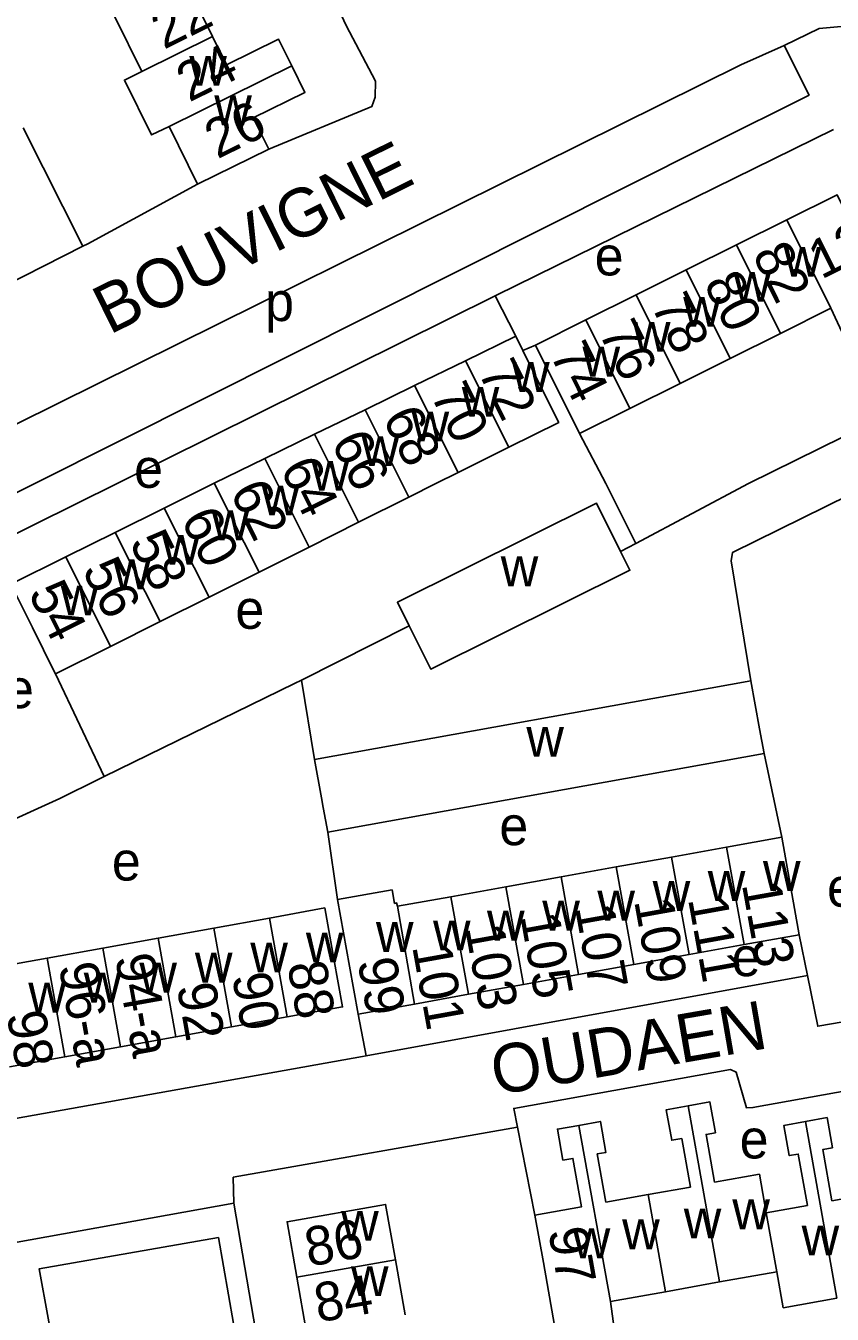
# Model space of a CAD drawing. Extents: x 157794 to 159375, y 380877 to 382306.
# Drawn here: x 158354 to 158437, y 381414.5 to 381547.1 of the extents above; entities that cross this region are included whole.
import ezdxf

# ---------------------------------------------------------------- set-up
doc = ezdxf.new("R2010")
doc.units = 0
for name, color, linetype in [('BLT_Basislijn', 7, 'Continuous'), ('BLT_Bebouwing', 7, 'Continuous'), ('BLT_Centroide', 7, 'Continuous'), ('BLT_Huisnummer', 7, 'Continuous'), ('BLT_Huisnummer_ tussenligend', 7, 'Continuous'), ('BLT_Huisnummer_reeks', 7, 'Continuous'), ('BLT_Onderverdeling_panden', 7, 'Continuous'), ('BLT_Straatnaam', 7, 'Continuous')]:
    doc.layers.add(name, color=color, linetype=linetype)

msp = doc.modelspace()

# ---------------------------------------------------------------- linework, layer by layer
at = {"layer": 'BLT_Basislijn'}
for p, q in [((158359.89, 381524.44), (158353.74, 381536.64)), ((158404.43, 381515.17), (158402.32, 381519.33)), ((158405.16, 381513.72), (158406.47, 381514.27)), ((158416.79, 381493.84), (158415.22, 381493.01)), ((158382.37, 381479.77), (158393.48, 381485.34)), ((158357.06, 381480.4), (158362.08, 381469.83)), ((158382.37, 381479.77), (158383.74, 381471.58)), ((158431.81, 381463.59), (158429.99, 381472.2)), ((158357.53, 381467.58), (158350.52, 381464.39)), ((158386.08, 381457.16), (158385.09, 381464.1)), ((158433.62, 381453.55), (158434.46, 381449.35)), ((158389.04, 381441.08), (158434.46, 381449.35)), ((158388.21, 381445.36), (158389.04, 381441.08)), ((158406.41, 381424.67), (158404.63, 381433.72)), ((158375.43, 381425.92), (158348.3, 381421.02)), ((158380.03, 381399.02), (158375.43, 381425.92))]:
    msp.add_line(p, q, dxfattribs=at)
for points in [[(158379.01, 381534.43), (158389.61, 381538.83), (158389.96, 381539.81), (158389.99, 381541.44), (158386.97, 381547.16), (158375.23, 381572.49), (158369.82, 381587.16)], [(158432.05, 381545.11), (158435.65, 381546.85), (158438.67, 381547.13), (158439.79, 381546.85), (158442.01, 381544.7), (158444.4, 381540.04)], [(158432.05, 381545.11), (158427.59, 381543.14), (158340.66, 381500), (158326.22, 381492.89), (158322.69, 381489.48), (158322.78, 381485.57), (158323.33, 381484.58)], [(158432.05, 381545.11), (158434.63, 381540.01), (158424.45, 381534.91), (158354.95, 381500), (158345.29, 381495.16), (158323.33, 381484.58)], [(158437.14, 381536.48), (158402.44, 381519.39), (158402.32, 381519.33)], [(158371.69, 381530.82), (158360.4, 381524.7), (158359.89, 381524.44)], [(158281.44, 381482.74), (158282.1, 381483.17), (158295.26, 381491.61), (158311.81, 381500), (158359.89, 381524.44)], [(158402.32, 381519.33), (158363.43, 381500), (158350.57, 381493.67)], [(158450.23, 381510.78), (158428.38, 381500), (158416.79, 381493.84)], [(158428.64, 381479.68), (158426.62, 381492.06), (158426.74, 381492.89), (158441.15, 381500), (158454.58, 381506.47)], [(158411, 381505.17), (158413.7, 381500), (158416.79, 381493.84)], [(158362.08, 381469.83), (158381.65, 381479.41), (158382.37, 381479.77)], [(158357.53, 381467.58), (158361.53, 381469.56), (158362.08, 381469.83)], [(158434.46, 381449.35), (158435.52, 381444.13), (158464.58, 381449.11)], [(158389.04, 381441.08), (158388.65, 381441.01), (158347.73, 381433.71), (158347.43, 381433.69)], [(158404.63, 381433.72), (158404.24, 381435.67), (158426.55, 381439.67), (158427.12, 381439.4), (158428.2, 381435.71), (158428.84, 381435.74), (158461.58, 381441.62), (158462.15, 381441.73)], [(158375.43, 381425.92), (158375.36, 381428.57), (158404.63, 381433.72)], [(158373.84, 381422.36), (158355.39, 381419.16), (158358.15, 381403.9), (158363.16, 381405.02), (158365.35, 381403.76), (158366.31, 381398.82), (158373.98, 381400.19), (158372.95, 381402.04), (158372.62, 381404.82), (158373.43, 381407.49), (158374.04, 381407.91), (158375, 381409.38), (158375.35, 381410.51), (158375.39, 381413.51), (158373.84, 381422.36)]]:
    msp.add_lwpolyline(points, dxfattribs=at)
at = {"layer": 'BLT_Bebouwing'}
for p, q in [((158365.95, 381542.44), (158363.17, 381548.08)), ((158371.69, 381530.82), (158368.75, 381536.78)), ((158379.01, 381534.43), (158371.69, 381530.82)), ((158427.17, 381524.58), (158432.35, 381527.15)), ((158421.99, 381522), (158427.17, 381524.58)), ((158416.82, 381519.43), (158421.99, 381522)), ((158411.64, 381516.85), (158416.82, 381519.43)), ((158436.88, 381518.05), (158431.7, 381515.47)), ((158406.47, 381514.27), (158411.64, 381516.85)), ((158431.7, 381515.47), (158426.52, 381512.9)), ((158404.43, 381515.17), (158399.27, 381512.65)), ((158405.16, 381513.72), (158404.43, 381515.17)), ((158411, 381505.17), (158406.47, 381514.27)), ((158426.52, 381512.9), (158421.35, 381510.32)), ((158399.27, 381512.65), (158394.03, 381510.09)), ((158394.03, 381510.09), (158388.93, 381507.61)), ((158421.35, 381510.32), (158416.17, 381507.74)), ((158388.93, 381507.61), (158383.73, 381505.08)), ((158416.17, 381507.74), (158411, 381505.17)), ((158383.73, 381505.08), (158378.6, 381502.57)), ((158378.6, 381502.57), (158373.41, 381500.04)), ((158378.6, 381502.57), (158383.17, 381493.47)), ((158388.26, 381496.02), (158393.43, 381498.61)), ((158363.22, 381494.98), (158368.25, 381497.48)), ((158383.17, 381493.47), (158388.26, 381496.02)), ((158358.14, 381492.46), (158363.22, 381494.98)), ((158378.03, 381490.89), (158383.17, 381493.47)), ((158352.48, 381489.64), (158358.14, 381492.46)), ((158372.87, 381488.31), (158378.03, 381490.89)), ((158367.85, 381485.8), (158372.87, 381488.31)), ((158362.73, 381483.23), (158367.85, 381485.8)), ((158357.06, 381480.4), (158362.73, 381483.23)), ((158428.64, 381479.68), (158383.74, 381471.58)), ((158383.74, 381471.58), (158384.44, 381467.66)), ((158429.99, 381472.2), (158385.09, 381464.1)), ((158420.46, 381461.55), (158426.13, 381462.57)), ((158426.13, 381462.57), (158431.81, 381463.59)), ((158414.78, 381460.53), (158420.46, 381461.55)), ((158409.1, 381459.51), (158414.78, 381460.53)), ((158397.75, 381457.46), (158403.42, 381458.48)), ((158403.42, 381458.48), (158409.1, 381459.51)), ((158392.27, 381456.48), (158397.75, 381457.46)), ((158379.08, 381455.27), (158373.36, 381454.23)), ((158367.64, 381453.2), (158361.93, 381452.17)), ((158373.36, 381454.23), (158367.64, 381453.2)), ((158433.62, 381453.55), (158427.95, 381452.53)), ((158361.93, 381452.17), (158356.21, 381451.14)), ((158427.95, 381452.53), (158422.27, 381451.5)), ((158356.21, 381451.14), (158350.49, 381450.11)), ((158416.59, 381450.48), (158410.91, 381449.46)), ((158422.27, 381451.5), (158416.59, 381450.48)), ((158410.91, 381449.46), (158405.24, 381448.43)), ((158405.24, 381448.43), (158399.56, 381447.41)), ((158394.01, 381446.41), (158388.21, 381445.36)), ((158399.56, 381447.41), (158394.01, 381446.41)), ((158375.19, 381444.06), (158380.91, 381445.09)), ((158369.47, 381443.03), (158375.19, 381444.06)), ((158363.76, 381442), (158369.47, 381443.03)), ((158358.04, 381440.97), (158363.76, 381442)), ((158352.32, 381439.94), (158358.04, 381440.97)), ((158392.05, 381420.08), (158393.05, 381414.39)), ((158425.42, 381417.79), (158431.31, 381418.84)), ((158382.91, 381412.6), (158381.9, 381418.29)), ((158419.85, 381416.79), (158425.42, 381417.79)), ((158414.18, 381415.78), (158419.85, 381416.79))]:
    msp.add_line(p, q, dxfattribs=at)
for points in [[(158375.84, 381554.34), (158377.18, 381551.63), (158371.78, 381548.96), (158373.23, 381546.04)], [(158373.23, 381546.04), (158374.67, 381543.11), (158380.03, 381545.76), (158381.39, 381543.02)], [(158368.75, 381536.78), (158366.96, 381535.9), (158364.16, 381541.56), (158365.95, 381542.44)], [(158381.39, 381543.02), (158382.74, 381540.28), (158377.41, 381537.65), (158379.01, 381534.43)], [(158432.35, 381527.15), (158437.52, 381529.73), (158442.05, 381520.62), (158441.81, 381520.5), (158443.25, 381517.6), (158438.24, 381515.11), (158436.88, 381518.05)], [(158403.72, 381503.74), (158408.86, 381506.31), (158406.52, 381511.01), (158405.16, 381513.72)], [(158398.5, 381501.14), (158403.72, 381503.74)], [(158393.43, 381498.61), (158396.21, 381500), (158398.5, 381501.14)], [(158368.25, 381497.48), (158373.32, 381500), (158373.41, 381500.04)], [(158415.22, 381493.01), (158412.76, 381497.97), (158392.26, 381487.79), (158393.48, 381485.34)], [(158393.48, 381485.34), (158395.69, 381480.9), (158416.18, 381491.08), (158415.22, 381493.01)], [(158357.06, 381480.4), (158356.98, 381480.58), (158354.69, 381485.19), (158352.48, 381489.64)], [(158429.99, 381472.2), (158429.52, 381474.76), (158428.64, 381479.68)], [(158384.44, 381467.66), (158384.62, 381466.66), (158385.09, 381464.1)], [(158431.81, 381463.59), (158432.75, 381458.39), (158433.62, 381453.55)], [(158386.08, 381457.16), (158391.71, 381458.17), (158391.96, 381456.78), (158392.18, 381456.82), (158392.27, 381456.48)], [(158388.21, 381445.36), (158387.31, 381450.31), (158386.08, 381457.16)], [(158380.91, 381445.09), (158386.62, 381446.12), (158385.73, 381451.06), (158384.78, 381456.3), (158379.08, 381455.27)], [(158418.06, 381426.79), (158422.41, 381427.57), (158421.52, 381432.56), (158420.49, 381432.38), (158419.93, 381435.53), (158422.17, 381435.93)], [(158422.17, 381435.93), (158424.42, 381436.33), (158424.99, 381433.16), (158424.02, 381432.99), (158424.9, 381428.07), (158429.51, 381428.89), (158430.22, 381424.92)], [(158434.25, 381434.31), (158436.48, 381434.71), (158437.03, 381431.61), (158436.04, 381431.43), (158436.98, 381426.16), (158441.37, 381426.94)], [(158406.41, 381424.67), (158411.22, 381425.53), (158410.32, 381430.52), (158409.3, 381430.34), (158408.73, 381433.53), (158410.94, 381433.92)], [(158410.94, 381433.92), (158413.15, 381434.32), (158413.71, 381431.13), (158412.83, 381430.97), (158413.71, 381426.02), (158418.06, 381426.79)], [(158430.22, 381424.92), (158434.46, 381425.68), (158433.52, 381430.96), (158432.58, 381430.8), (158432.03, 381433.91), (158434.25, 381434.31)], [(158381.9, 381418.29), (158380.9, 381423.99), (158391.04, 381425.78), (158392.05, 381420.08)], [(158408.68, 381411.95), (158407.28, 381419.79), (158406.41, 381424.67)], [(158431.31, 381418.84), (158431.97, 381415.14), (158437.5, 381416.13)], [(158408.68, 381411.95), (158414.56, 381413), (158414.18, 381415.78)]]:
    msp.add_lwpolyline(points, dxfattribs=at)
at = {"layer": 'BLT_Onderverdeling_panden'}
for p, q in [((158373.23, 381546.04), (158365.95, 381542.44)), ((158381.39, 381543.02), (158368.75, 381536.78)), ((158436.88, 381518.05), (158432.35, 381527.15)), ((158431.7, 381515.47), (158427.17, 381524.58)), ((158426.52, 381512.9), (158421.99, 381522)), ((158421.35, 381510.32), (158416.82, 381519.43)), ((158416.17, 381507.74), (158411.64, 381516.85)), ((158399.27, 381512.65), (158403.72, 381503.74)), ((158394.03, 381510.09), (158398.5, 381501.14)), ((158388.93, 381507.61), (158393.43, 381498.61)), ((158383.73, 381505.08), (158388.26, 381496.02)), ((158373.41, 381500.04), (158378.03, 381490.89)), ((158368.25, 381497.48), (158372.87, 381488.31)), ((158363.22, 381494.98), (158367.85, 381485.8)), ((158358.14, 381492.46), (158362.73, 381483.23)), ((158427.95, 381452.53), (158426.13, 381462.57)), ((158422.27, 381451.5), (158420.46, 381461.55)), ((158416.59, 381450.48), (158414.78, 381460.53)), ((158405.24, 381448.43), (158403.42, 381458.48)), ((158410.91, 381449.46), (158409.1, 381459.51)), ((158399.56, 381447.41), (158397.75, 381457.46)), ((158394.01, 381446.41), (158392.27, 381456.48)), ((158380.91, 381445.09), (158379.08, 381455.27)), ((158369.47, 381443.03), (158367.64, 381453.2)), ((158375.19, 381444.06), (158373.36, 381454.23)), ((158363.76, 381442), (158361.93, 381452.17)), ((158358.04, 381440.97), (158356.21, 381451.14)), ((158422.17, 381435.93), (158425.42, 381417.79)), ((158410.94, 381433.92), (158414.18, 381415.78)), ((158434.25, 381434.31), (158437.5, 381416.13)), ((158418.06, 381426.79), (158419.85, 381416.79)), ((158430.22, 381424.92), (158431.31, 381418.84)), ((158381.9, 381418.29), (158392.05, 381420.08))]:
    msp.add_line(p, q, dxfattribs=at)

# ---------------------------------------------------------------- texts
at = {"layer": 'BLT_Centroide'}
for s, p in [('w', (158370.84, 381540.97)), ('w', (158373.41, 381536.91)), ('e', (158412.56, 381521.44)), ('w', (158432.02, 381521.31)), ('w', (158426.84, 381518.73)), ('p', (158378.64, 381516.74)), ('w', (158421.67, 381516.16)), ('w', (158416.5, 381513.58)), ('w', (158411.31, 381511.02)), ('w', (158404.06, 381509.45)), ('w', (158398.88, 381506.89)), ('w', (158393.72, 381504.34)), ('w', (158388.58, 381501.81)), ('e', (158365.16, 381499.57)), ('w', (158383.42, 381499.27)), ('w', (158378.3, 381496.72)), ('w', (158373.14, 381494.17)), ('w', (158368.05, 381491.64)), ('w', (158363, 381489.12)), ('w', (158402.89, 381489.44)), ('w', (158357.61, 381486.42)), ('e', (158375.58, 381485.05)), ('e', (158351.87, 381476.88)), ('w', (158405.53, 381471.88)), ('e', (158402.75, 381462.77)), ('e', (158362.87, 381459.13)), ('w', (158429.88, 381458.06)), ('w', (158424.2, 381457.03)), ('w', (158418.53, 381456)), ('e', (158436.47, 381456.43)), ('w', (158407.17, 381453.97)), ('w', (158412.84, 381455)), ('w', (158401.48, 381452.94)), ('w', (158390.05, 381451.78)), ('w', (158395.92, 381451.94)), ('w', (158382.84, 381450.69)), ('w', (158371.42, 381448.62)), ('w', (158377.12, 381449.66)), ('e', (158426.66, 381449.28)), ('w', (158365.7, 381447.59)), ('w', (158359.98, 381446.56)), ('w', (158354.27, 381445.53)), ('e', (158427.48, 381430.51)), ('w', (158421.73, 381422.28)), ('w', (158426.73, 381423.22)), ('w', (158386.47, 381422.03)), ('w', (158415.39, 381421.16)), ('w', (158410.3, 381420.23)), ('w', (158433.86, 381420.52)), ('w', (158387.48, 381416.34))]:
    msp.add_text(s, height=4, dxfattribs=at).set_placement(p)
at = {"layer": 'BLT_Huisnummer'}
for s, rotation, p in [('26', 26.2747, (158373.73, 381533.38)), ('131', 26.4579, (158435.88, 381520.99)), ('82', 296.4213, (158428.73, 381523.62)), ('78', 296.4213, (158418.31, 381518.36)), ('74', 296.4213, (158407.9, 381513.34)), ('70', 296.4213, (158395.61, 381509.16)), ('66', 296.4213, (158385.38, 381504.25)), ('62', 296.4213, (158374.97, 381499.15)), ('58', 296.4213, (158364.62, 381493.94)), ('54', 296.4213, (158354.21, 381488.74)), ('113', 280.2212, (158427.7, 381458.75)), ('107', 280.2212, (158410.52, 381456.38)), ('103', 280.2212, (158399.2, 381454.31)), ('88', 280.2062, (158380.91, 381450.5)), ('99', 280.2212, (158388.14, 381450.85)), ('92', 280.2062, (158369.53, 381448.26)), ('86', 10.0202, (158383.11, 381419.36))]:
    msp.add_text(s, height=4, rotation=rotation, dxfattribs=at).set_placement(p)
at = {"layer": 'BLT_Huisnummer_ tussenligend'}
for s, rotation, p in [('22', 26.2747, (158368.22, 381544.67)), ('24', 26.2747, (158370.83, 381539.24)), ('80', 296.4213, (158423.73, 381520.61)), ('76', 296.4213, (158412.92, 381515.59)), ('72', 296.4213, (158400.51, 381511.53)), ('68', 296.4213, (158390.67, 381506.76)), ('64', 296.4213, (158380.13, 381501.54)), ('60', 296.4213, (158369.91, 381496.33)), ('56', 296.4213, (158359.76, 381491.12)), ('109', 280.2212, (158416.61, 381457.04)), ('111', 280.2212, (158422.16, 381457.23)), ('105', 280.2212, (158404.89, 381455.5)), ('101', 280.2212, (158393.77, 381452.34)), ('90', 280.2062, (158375.22, 381449.32)), ('98', 280.2062, (158352.02, 381445.38)), ('84', 10.0193, (158384.09, 381413.61))]:
    msp.add_text(s, height=4, rotation=rotation, dxfattribs=at).set_placement(p)
at = {"layer": 'BLT_Huisnummer_reeks'}
for s, rotation, p in [('96-a', 280.2062, (158357.39, 381450.37)), ('94-a', 280.2062, (158363.19, 381451.26)), ('97', 280.1184, (158407.77, 381423.11))]:
    msp.add_text(s, height=4, rotation=rotation, dxfattribs=at).set_placement(p)
at = {"layer": 'BLT_Straatnaam'}
for s, rotation, p in [('BOUVIGNE', 26.3903, (158362.62, 381515.29)), ('OUDAEN', 9.8134, (158402.36, 381437.01))]:
    msp.add_text(s, height=5, rotation=rotation, dxfattribs=at).set_placement(p)

doc.saveas('drawing.dxf')
